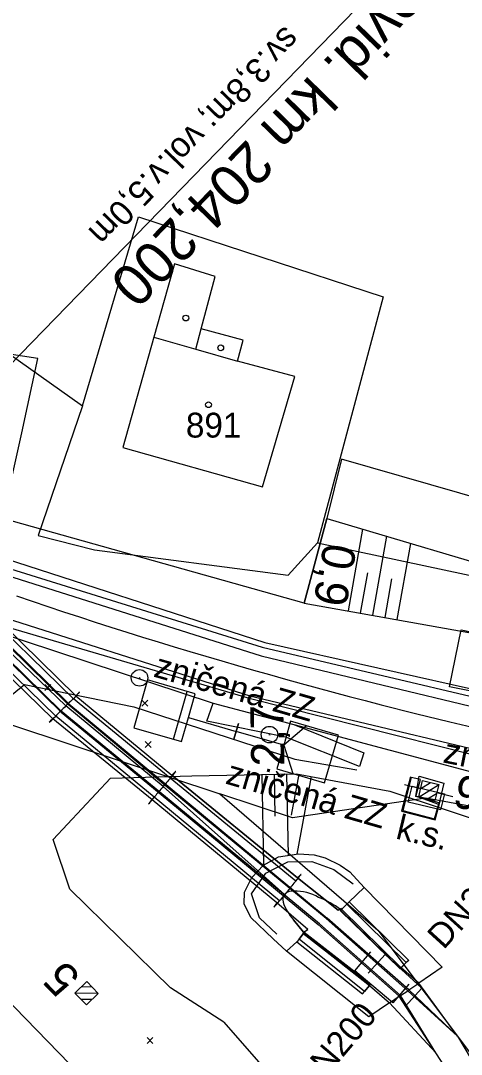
# Model space of a CAD drawing. Extents: x -800194 to -799078, y -1007177 to -1006597.
# Drawn here: x -799745.3 to -799718.7, y -1007007.9 to -1006945.4 of the extents above; entities that cross this region are included whole.
import ezdxf

# ---------------------------------------------------------------- set-up
doc = ezdxf.new("R2010")
doc.units = 0
for name, color, linetype in [('02_Osa_koleje', 7, 'Continuous'), ('_návrh', 7, 'Continuous'), ('Vrstva 11', 7, 'Continuous'), ('Vrstva 12', 7, 'Continuous'), ('Vrstva 16', 7, 'Continuous'), ('Vrstva 17', 7, 'Continuous'), ('Vrstva 18', 7, 'Continuous'), ('Vrstva 23', 7, 'Continuous'), ('Vrstva 25', 7, 'Continuous'), ('Vrstva 4', 7, 'Continuous'), ('Vrstva 43', 7, 'Continuous'), ('Vrstva 48', 7, 'Continuous'), ('Vrstva 49', 7, 'Continuous'), ('Vrstva 5', 7, 'Continuous'), ('Vrstva 50', 7, 'Continuous'), ('Vrstva 55', 7, 'Continuous'), ('Vrstva 56', 7, 'Continuous'), ('Vrstva 57', 7, 'Continuous'), ('Vrstva 59', 7, 'Continuous'), ('Vrstva 7', 7, 'Continuous')]:
    doc.layers.add(name, color=color, linetype=linetype)

msp = doc.modelspace()

# ---------------------------------------------------------------- linework, layer by layer
at = {"layer": '02_Osa_koleje'}
msp.add_lwpolyline([(-799745.551, -1006980.175), (-799744.604, -1006980.496), (-799743.656, -1006980.814), (-799742.707, -1006981.129), (-799741.757, -1006981.441), (-799740.806, -1006981.749), (-799739.853, -1006982.055), (-799738.9, -1006982.357), (-799737.946, -1006982.656), (-799736.991, -1006982.951), (-799736.034, -1006983.244), (-799735.077, -1006983.533), (-799734.119, -1006983.819), (-799733.16, -1006984.102), (-799732.199, -1006984.381), (-799731.238, -1006984.657), (-799730.276, -1006984.93), (-799729.313, -1006985.2), (-799728.35, -1006985.467), (-799727.385, -1006985.73), (-799726.419, -1006985.989), (-799725.453, -1006986.246), (-799724.485, -1006986.499), (-799723.517, -1006986.749)], dxfattribs=at)
msp.add_arc((-799651.022, -1006703.891), 292, 255.62486, 308.20516, dxfattribs=at)
at = {"layer": '_návrh'}
msp.add_lwpolyline([(-799821.595, -1006948.007), (-799811.064, -1006954.324), (-799803.753, -1006958.707), (-799793.935, -1006964.581), (-799784.224, -1006971.671), (-799782.913, -1006972.63), (-799767.418, -1006984.719), (-799752.333, -1006998.173), (-799735.027, -1007015.997), (-799721.623, -1007030.81), (-799713.555, -1007039.726), (-799713.111, -1007040.218)], dxfattribs=at)
at = {"layer": 'Vrstva 11'}
for p, q in [((-799721.139, -1006991.823), (-799722.111, -1006991.588)), ((-799721.233, -1006992.314), (-799720.055, -1006991.593)), ((-799721.138, -1006991.816), (-799720.542, -1006991.451)), ((-799720.718, -1006992.438), (-799720.18, -1006992.109)), ((-799720.167, -1006992.057), (-799719.195, -1006992.29)), ((-799740.621, -1007004.194), (-799742.031, -1007004.173)), ((-799740.986, -1007003.813), (-799741.655, -1007003.803)), ((-799741.001, -1007004.563), (-799741.662, -1007004.553))]:
    msp.add_line(p, q, dxfattribs=at)
for points in [[(-799721.022, -1006991.336), (-799720.05, -1006991.57), (-799720.284, -1006992.542), (-799721.256, -1006992.308)], [(-799741.336, -1007004.888), (-799742.033, -1007004.171), (-799741.316, -1007003.474), (-799740.619, -1007004.191)]]:
    msp.add_lwpolyline(points, close=True, dxfattribs=at)
at = {"layer": 'Vrstva 12'}
msp.add_lwpolyline([(-799721.236, -1006991.07), (-799719.737, -1006991.48), (-799720.049, -1006992.784), (-799721.435, -1006992.272), (-799721.236, -1006991.07)], dxfattribs=at)
at = {"layer": 'Vrstva 16'}
for p, q in [((-799725.462, -1006998.653), (-799724.55, -1006997.8)), ((-799728.219, -1007000.489), (-799728.813, -1006999.75)), ((-799721.913, -1007004.037), (-799726.857, -1006999.659)), ((-799727.952, -1007000.326), (-799728.231, -1007000.559)), ((-799728.231, -1007000.559), (-799724.23, -1007003.721)), ((-799727.258, -1006999.988), (-799722.361, -1007004.328)), ((-799728.622, -1007001.076), (-799729.241, -1007001.641)), ((-799721.857, -1007003.981), (-799721.255, -1007003.58)), ((-799723.028, -1007004.76), (-799722.434, -1007004.367))]:
    msp.add_line(p, q, dxfattribs=at)
for points in [[(-799726.857, -1006999.659), (-799736.574, -1006991.623), (-799742.439, -1006986.725), (-799754.518, -1006974.879), (-799763.734, -1006965.993), (-799777.293, -1006954.374), (-799779.945, -1006952.099), (-799783.722, -1006948.693)], [(-799783.708, -1006948.669), (-799779.9, -1006952.065), (-799777.252, -1006954.333), (-799763.672, -1006965.935), (-799754.476, -1006974.829), (-799742.393, -1006986.703), (-799736.524, -1006991.578), (-799726.778, -1006999.642)], [(-799784.356, -1006949.5), (-799780.347, -1006952.62), (-799777.716, -1006954.827), (-799764.168, -1006966.436), (-799754.935, -1006975.363), (-799742.857, -1006987.188), (-799736.94, -1006992.081), (-799727.324, -1007000.028)], [(-799727.258, -1006999.988), (-799736.887, -1006992.032), (-799742.859, -1006987.132), (-799754.894, -1006975.337), (-799764.135, -1006966.374), (-799777.698, -1006954.783), (-799780.331, -1006952.581), (-799784.321, -1006949.462)], [(-799779.465, -1006951.506), (-799778.251, -1006952.583), (-799776.738, -1006953.884), (-799763.224, -1006965.504), (-799753.999, -1006974.421), (-799741.964, -1006986.204), (-799736.168, -1006991.012), (-799728.577, -1006997.215), (-799726.123, -1006999.163)], [(-799727.952, -1007000.326), (-799729.82, -1006998.717), (-799737.37, -1006992.486), (-799743.358, -1006987.594), (-799755.401, -1006975.883), (-799764.592, -1006966.926), (-799778.073, -1006955.449), (-799779.598, -1006954.142), (-799780.843, -1006953.125)], [(-799724.268, -1007005.601), (-799729.241, -1007001.641), (-799730.043, -1007000.896), (-799731.391, -1006999.609), (-799731.807, -1006998.789), (-799731.776, -1006998.081), (-799731.332, -1006997.192), (-799730.628, -1006996.451), (-799729.736, -1006995.947), (-799728.528, -1006995.755), (-799727.566, -1006995.827), (-799726.904, -1006996.009), (-799726.001, -1006996.45), (-799725.419, -1006996.855), (-799724.55, -1006997.8), (-799719.837, -1007002.616)], [(-799719.837, -1007002.616), (-799721.255, -1007003.58), (-799722.309, -1007002.649), (-799722.019, -1007002.331), (-799725.605, -1006998.806), (-799725.462, -1006998.653), (-799721.848, -1007002.204), (-799722.019, -1007002.331)], [(-799726.123, -1006999.163), (-799725.923, -1006999.111), (-799725.92, -1006999.107), (-799725.969, -1006999.167)], [(-799725.605, -1006998.806), (-799725.969, -1006999.167), (-799725.978, -1006999.12)], [(-799727.324, -1007000.028), (-799722.434, -1007004.367), (-799722.361, -1007004.328), (-799721.913, -1007004.037), (-799721.857, -1007003.981), (-799726.778, -1006999.642)], [(-799724.23, -1007003.721), (-799724.534, -1007004.077), (-799728.488, -1007000.913), (-799728.199, -1007000.524)], [(-799728.231, -1007000.559), (-799728.25, -1007000.58), (-799728.201, -1007000.516), (-799728.199, -1007000.524), (-799728.219, -1007000.489)], [(-799728.488, -1007000.913), (-799728.622, -1007001.076), (-799724.647, -1007004.218), (-799724.534, -1007004.077)], [(-799724.23, -1007003.721), (-799723.028, -1007004.76), (-799724.268, -1007005.601)]]:
    msp.add_lwpolyline(points, dxfattribs=at)
for centre, major_axis, ratio, start_param, end_param in [((-799728.904, -1006998.513), (-0.566, -0.095), 0.888473, 4.396597, 6.415472), ((-799729.06, -1007000.766), (-2.796, -1.224), 0.88479, 3.718308, 4.259024), ((-799725.41, -1006997.773), (-4.211, 0.231), 0.818659, 0.330695, 0.676051), ((-799730.273, -1007003.369), (-6.212, -1.397), 0.847151, 3.77745, 4.035936), ((-799727.773, -1007000.273), (1.862, 1.216), 0.026669, 5.99696, 6.747447), ((-799726.195, -1006999.167), (-2.024, -1.323), 0.007629, 6.252324, 6.798297)]:
    msp.add_ellipse(centre, major_axis=major_axis, ratio=ratio, start_param=start_param, end_param=end_param, dxfattribs=at)
at = {"layer": 'Vrstva 17'}
for points in [[(-799726.806, -1006975.491), (-799728.174, -1006980.607), (-799746.39, -1006975.498), (-799745.242, -1006970.318), (-799744.263, -1006965.815), (-799756.721, -1006963.941)], [(-799695.807, -1006967.611), (-799698.37, -1006979.283), (-799711.621, -1006976.014), (-799725.913, -1006971.918), (-799726.806, -1006975.491)], [(-799746.564, -1006986.717), (-799745.074, -1006985.521), (-799738.458, -1006986.883), (-799728.745, -1006990.03), (-799724.988, -1006990.685)], [(-799721.747, -1006991.106), (-799722.3, -1006993.177), (-799720.272, -1006993.705), (-799719.96, -1006992.563)], [(-799729.82, -1007000.617), (-799730.868, -1006999.634), (-799731.355, -1006998.181), (-799730.498, -1006996.925), (-799729.155, -1006996.246), (-799727.711, -1006996.213), (-799726.389, -1006996.698), (-799725.227, -1006997.578)]]:
    msp.add_lwpolyline(points, dxfattribs=at)
at = {"layer": 'Vrstva 18'}
for p, q in [((-799754.68, -1006975.182), (-799715.262, -1006934.616)), ((-799728.577, -1006997.215), (-799736.168, -1006991.012)), ((-799729.364, -1006998.225), (-799736.701, -1006991.694)), ((-799729.82, -1006998.717), (-799737.37, -1006992.486)), ((-799726.123, -1006999.163), (-799728.577, -1006997.215)), ((-799727.952, -1007000.326), (-799729.82, -1006998.717)), ((-799725.98, -1006999.167), (-799722.374, -1007002.692)), ((-799722.407, -1007002.695), (-799725.98, -1006999.2)), ((-799722.019, -1007002.331), (-799725.605, -1006998.806)), ((-799728.813, -1006999.75), (-799728.219, -1007000.489)), ((-799728.199, -1007000.524), (-799728.488, -1007000.913)), ((-799724.23, -1007003.721), (-799728.231, -1007000.559)), ((-799728.199, -1007000.524), (-799728.201, -1007000.516)), ((-799724.197, -1007003.62), (-799728.169, -1007000.506)), ((-799728.168, -1007000.512), (-799724.201, -1007003.621)), ((-799724.534, -1007004.077), (-799728.488, -1007000.913)), ((-799724.238, -1007003.715), (-799728.25, -1007000.58)), ((-799722.374, -1007002.692), (-799722.372, -1007002.691))]:
    msp.add_line(p, q, dxfattribs=at)
for points in [[(-799728.689, -1006997.417), (-799736.272, -1006991.186), (-799742.111, -1006986.385), (-799754.178, -1006974.631), (-799763.368, -1006965.72), (-799777.061, -1006954.31)], [(-799776.738, -1006953.884), (-799763.224, -1006965.504), (-799753.999, -1006974.421), (-799741.964, -1006986.204), (-799736.168, -1006991.012)], [(-799736.701, -1006991.694), (-799742.573, -1006986.82), (-799754.68, -1006975.182), (-799763.887, -1006966.256), (-799777.391, -1006954.732)], [(-799737.37, -1006992.486), (-799743.358, -1006987.594), (-799755.401, -1006975.883), (-799764.592, -1006966.926), (-799778.073, -1006955.449)], [(-799729.664, -1006998.596), (-799737.245, -1006992.341), (-799743.186, -1006987.438), (-799755.222, -1006975.72), (-799764.444, -1006966.802), (-799777.959, -1006955.323)], [(-799725.98, -1006999.167), (-799725.92, -1006999.107), (-799725.923, -1006999.111), (-799722.309, -1007002.649)], [(-799725.969, -1006999.167), (-799725.98, -1006999.167), (-799725.98, -1006999.2), (-799725.968, -1006999.201)], [(-799725.605, -1006998.806), (-799725.969, -1006999.167), (-799725.968, -1006999.201), (-799722.404, -1007002.693)], [(-799728.201, -1007000.516), (-799728.25, -1007000.58), (-799728.231, -1007000.559)], [(-799724.194, -1007003.649), (-799728.201, -1007000.516), (-799728.169, -1007000.506)], [(-799728.169, -1007000.506), (-799728.168, -1007000.512), (-799728.199, -1007000.524)], [(-799722.309, -1007002.649), (-799722.321, -1007002.641), (-799722.374, -1007002.692), (-799722.407, -1007002.695), (-799722.404, -1007002.693), (-799722.372, -1007002.691), (-799722.019, -1007002.331), (-799722.309, -1007002.649)], [(-799724.201, -1007003.621), (-799724.197, -1007003.656), (-799724.534, -1007004.077), (-799724.23, -1007003.721)], [(-799724.194, -1007003.649), (-799724.238, -1007003.715), (-799724.23, -1007003.721)], [(-799724.197, -1007003.656), (-799724.194, -1007003.649), (-799724.197, -1007003.62), (-799724.201, -1007003.621)]]:
    msp.add_lwpolyline(points, dxfattribs=at)
for centre, major_axis, ratio, start_param, end_param in [((-799742.548, -1006987.401), (-0.826, -1.378), 0.12501, 3.399125, 3.961351), ((-799742.949, -1006987.371), (1.204, 1.399), 0.014573, 5.978594, 6.879596), ((-799742.617, -1006986.915), (0.711, 0.695), 0.037234, 0.742353, 2.460401), ((-799742.474, -1006986.496), (1.116, 1.298), 0.059378, 3.418673, 3.953091), ((-799742.2, -1006986.605), (-1.386, -1.202), 0.01146, 5.69132, 6.569057), ((-799736.745, -1006991.75), (0.647, 0.768), 0.002373, 0.747313, 2.45121), ((-799736.897, -1006992.163), (-0.963, -1.369), 0.041864, 3.408659, 3.947328), ((-799737.23, -1006992.158), (1.296, 1.385), 0.007101, 5.99726, 6.885866), ((-799736.715, -1006991.366), (0.854, 1.349), 0.064947, 3.376238, 3.945747), ((-799736.371, -1006991.391), (-1.212, -1.352), 0.012722, 5.667277, 6.576621), ((-799729.164, -1006998.01), (-0.65, -0.786), 0.017237, 3.872792, 5.567675), ((-799729.601, -1006998.375), (1.227, 1.391), 0.038982, 5.50568, 5.9942), ((-799729.675, -1006998.422), (1.311, 1.425), 0.009263, 6.006131, 6.851805), ((-799728.904, -1006998.513), (-0.566, -0.095), 0.888473, 4.396597, 6.415472), ((-799729.06, -1007000.766), (2.796, 1.224), 0.88479, 0.576715, 1.117431), ((-799728.95, -1006997.634), (-1.036, -1.326), 0.024932, 0.238319, 0.779035), ((-799725.41, -1006997.773), (-4.211, 0.231), 0.818659, 0.330695, 0.676051), ((-799730.273, -1007003.369), (-6.212, -1.397), 0.847151, 3.77745, 4.035936), ((-799728.754, -1006997.452), (-1.245, -1.521), 0.021997, 5.712311, 6.543003), ((-799727.773, -1007000.273), (1.862, 1.216), 0.026669, 5.99696, 6.747447), ((-799726.195, -1006999.167), (-2.024, -1.323), 0.007629, 6.252324, 6.798297)]:
    msp.add_ellipse(centre, major_axis=major_axis, ratio=ratio, start_param=start_param, end_param=end_param, dxfattribs=at)
at = {"layer": 'Vrstva 23'}
msp.add_lwpolyline([(-799721.159, -1006991.27), (-799721.712, -1006991.14), (-799722.223, -1006993.135), (-799720.312, -1006993.651), (-799720.015, -1006992.683), (-799721.422, -1006992.285), (-799721.159, -1006991.27)], dxfattribs=at)
at = {"layer": 'Vrstva 25'}
msp.add_lwpolyline([(-799721.886, -1006992.632), (-799721.652, -1006991.66), (-799719.708, -1006992.128), (-799719.942, -1006993.1), (-799721.886, -1006992.632)], dxfattribs=at)
at = {"layer": 'Vrstva 4'}
for points in [[(-799766.319, -1006970.565), (-799760.949, -1006972.542), (-799747.638, -1006977.46), (-799730.549, -1006982.982), (-799710.066, -1006987.578), (-799704.728, -1006988.346), (-799693.001, -1006990.373), (-799682.434, -1006991.64), (-799671.27, -1006992.619), (-799659.31, -1006993.026), (-799648.69, -1006993.125), (-799637.398, -1006992.704), (-799625.913, -1006992.175), (-799614.965, -1006990.831), (-799603.911, -1006989.312), (-799592.728, -1006987.172), (-799581.605, -1006984.547), (-799570.583, -1006981.598), (-799559.909, -1006978.216), (-799542.956, -1006972.25), (-799531.79, -1006967.658), (-799521.285, -1006962.191), (-799511.236, -1006957.129)], [(-799779.678, -1006964.304), (-799766.319, -1006970.565), (-799761.253, -1006973.176), (-799747.77, -1006978.421), (-799730.774, -1006983.8), (-799710.333, -1006988.709), (-799704.916, -1006989.741), (-799693.131, -1006991.407), (-799682.585, -1006992.929), (-799671.325, -1006993.879), (-799659.363, -1006994.45), (-799648.66, -1006994.501), (-799637.23, -1006994.127), (-799626.066, -1006993.335), (-799614.788, -1006992.17), (-799603.669, -1006990.506), (-799592.467, -1006988.452), (-799581.281, -1006985.916), (-799570.22, -1006982.998), (-799559.296, -1006979.606), (-799542.375, -1006973.485), (-799531.236, -1006968.774), (-799520.48, -1006963.762), (-799510.394, -1006958.536)], [(-799776.864, -1006969.085), (-799770.965, -1006971.646), (-799761.91, -1006975.649), (-799748.544, -1006980.777), (-799731.457, -1006986.215), (-799711.132, -1006991.054), (-799705.482, -1006992.16), (-799693.53, -1006994.084), (-799682.801, -1006995.384), (-799671.514, -1006996.319), (-799659.449, -1006996.851), (-799648.588, -1006996.949), (-799637.262, -1006996.573), (-799625.835, -1006995.773), (-799614.546, -1006994.586), (-799603.199, -1006992.945), (-799591.969, -1006990.857), (-799580.647, -1006988.335), (-799569.534, -1006985.311), (-799558.557, -1006981.947), (-799541.405, -1006975.739), (-799530.263, -1006971.071), (-799519.455, -1006966), (-799509.248, -1006960.724)], [(-799776.864, -1006969.085), (-799771.262, -1006971.982), (-799762.131, -1006976.093), (-799748.706, -1006981.286), (-799731.51, -1006986.353), (-799711.222, -1006991.459), (-799705.527, -1006992.587), (-799693.582, -1006994.543), (-799682.85, -1006995.904), (-799671.5, -1006996.805), (-799659.556, -1006997.356), (-799648.616, -1006997.341), (-799637.276, -1006997.071), (-799625.828, -1006996.297), (-799614.43, -1006995.109), (-799603.18, -1006993.475), (-799591.849, -1006991.264), (-799580.564, -1006988.698), (-799569.449, -1006985.746), (-799558.385, -1006982.386), (-799541.268, -1006976.227), (-799530.102, -1006971.505), (-799519.398, -1006966.36), (-799509.087, -1006961.127)], [(-799779.011, -1006963.023), (-799770.632, -1006967.944), (-799766.319, -1006970.565), (-799761.021, -1006972.82), (-799747.748, -1006977.966), (-799730.719, -1006983.271), (-799710.195, -1006988.108), (-799704.765, -1006989.181), (-799693.072, -1006990.965), (-799682.554, -1006992.238), (-799671.266, -1006993.222), (-799659.388, -1006993.765), (-799648.658, -1006993.824), (-799637.385, -1006993.531), (-799625.769, -1006992.728), (-799614.9, -1006991.542), (-799603.91, -1006989.963), (-799592.572, -1006987.892), (-799581.421, -1006985.419), (-799570.327, -1006982.332), (-799559.429, -1006979.066), (-799542.601, -1006973.013), (-799531.454, -1006968.25), (-799520.744, -1006963.214)], [(-799776.864, -1006969.085), (-799771.693, -1006972.522), (-799762.217, -1006976.394), (-799748.898, -1006981.647), (-799733.68, -1006986.66), (-799728.795, -1006987.945), (-799711.349, -1006992.599), (-799705.744, -1006994.116), (-799693.689, -1006996.09), (-799689.347, -1006996.226), (-799688.222, -1006996.296), (-799683.105, -1006997.407), (-799671.667, -1006998.275)], [(-799734.064, -1006987.737), (-799733.68, -1006986.66), (-799728.795, -1006987.945), (-799724.58, -1006989.646), (-799724.833, -1006990.487), (-799729.281, -1006988.715), (-799734.064, -1006987.737)]]:
    msp.add_lwpolyline(points, dxfattribs=at)
at = {"layer": 'Vrstva 43'}
for points in [[(-799721.858, -1007003.626), (-799722.831, -1007004.768), (-799725.115, -1007002.822), (-799724.142, -1007001.68)], [(-799724.303, -1007002.961), (-799723.293, -1007001.851), (-799721.075, -1007003.871), (-799722.084, -1007004.98)]]:
    msp.add_lwpolyline(points, dxfattribs=at)
at = {"layer": 'Vrstva 48'}
for p, q in [((-799725.506, -1006981.082), (-799724.627, -1006976.139)), ((-799724.029, -1006981.344), (-799723.18, -1006976.569)), ((-799722.552, -1006981.607), (-799721.733, -1006977)), ((-799724.767, -1006981.213), (-799724.335, -1006978.784)), ((-799723.291, -1006981.476), (-799722.873, -1006979.13)), ((-799730.742, -1006990.964), (-799730.628, -1006996.451)), ((-799729.993, -1006990.948), (-799729.94, -1006993.49)), ((-799729.243, -1006990.933), (-799729.14, -1006995.852)), ((-799728.495, -1006990.947), (-799728.955, -1006993.422)), ((-799727.758, -1006991.084), (-799728.628, -1006995.771))]:
    msp.add_line(p, q, dxfattribs=at)
at = {"layer": 'Vrstva 49'}
for p, q in [((-799743.837, -1006985.534), (-799743.483, -1006985.888)), ((-799743.837, -1006985.888), (-799743.483, -1006985.534)), ((-799737.98, -1006986.471), (-799737.626, -1006986.825)), ((-799737.98, -1006986.825), (-799737.626, -1006986.471)), ((-799737.782, -1006988.977), (-799737.428, -1006989.331)), ((-799737.782, -1006989.331), (-799737.428, -1006988.977)), ((-799718.907, -1007006.786), (-799721.255, -1007003.58)), ((-799718.907, -1007006.786), (-799721.857, -1007003.981)), ((-799720.214, -1007007.792), (-799723.028, -1007004.76)), ((-799722.361, -1007004.328), (-799722.434, -1007004.367)), ((-799720.214, -1007007.792), (-799722.434, -1007004.367)), ((-799720.214, -1007007.792), (-799722.361, -1007004.328)), ((-799737.668, -1007006.857), (-799737.314, -1007007.211)), ((-799737.668, -1007007.211), (-799737.314, -1007006.857))]:
    msp.add_line(p, q, dxfattribs=at)
for points in [[(-799728.174, -1006980.607), (-799726.806, -1006975.491), (-799714.47, -1006979.159), (-799704.928, -1006981.248), (-799699.097, -1006983.466), (-799688.779, -1006985.763), (-799678.423, -1006987.219), (-799669.363, -1006989.921)], [(-799728.174, -1006980.607), (-799715.637, -1006982.837), (-799705.851, -1006983.743), (-799700.586, -1006985.508), (-799691.67, -1006987.253), (-799678.693, -1006988.601), (-799669.363, -1006989.921)], [(-799733.039, -1007005.939), (-799736.26, -1007003.86), (-799742.34, -1006997.896), (-799743.342, -1006994.901), (-799739.871, -1006991.182), (-799734.968, -1006991.052), (-799728.642, -1006990.92), (-799723.01, -1006991.966), (-799716.141, -1006994.243), (-799710.319, -1006994.817)], [(-799723.028, -1007004.76), (-799724.268, -1007005.601), (-799729.241, -1007001.641), (-799730.043, -1007000.896), (-799731.391, -1006999.609), (-799731.807, -1006998.789), (-799731.776, -1006998.081), (-799731.332, -1006997.192), (-799730.628, -1006996.451), (-799729.736, -1006995.947), (-799728.528, -1006995.755), (-799727.566, -1006995.827), (-799726.904, -1006996.009), (-799726.001, -1006996.45), (-799725.419, -1006996.855), (-799724.55, -1006997.8), (-799719.837, -1007002.616), (-799721.255, -1007003.58)], [(-799718.907, -1007006.786), (-799721.913, -1007004.037), (-799721.857, -1007003.981)], [(-799733.039, -1007005.939), (-799730.086, -1007009.294), (-799720.161, -1007021.94)], [(-799718.907, -1007006.786), (-799714.515, -1007014.16), (-799704.214, -1007027.237), (-799692.017, -1007040.081), (-799674.887, -1007054.948)], [(-799676.078, -1007055.763), (-799692.866, -1007041.408), (-799705.479, -1007027.95), (-799715.681, -1007014.777), (-799720.214, -1007007.792)]]:
    msp.add_lwpolyline(points, dxfattribs=at)
at = {"layer": 'Vrstva 5'}
msp.add_lwpolyline([(-799715.76, -1006982.82), (-799716.453, -1006986.251), (-799719.394, -1006985.657), (-799718.701, -1006982.227)], close=True, dxfattribs=at)
at = {"layer": 'Vrstva 50'}
for p, q in [((-799738.172, -1006985.111), (-799738.076, -1006985.139)), ((-799730.319, -1006988.54), (-799730.223, -1006988.568))]:
    msp.add_line(p, q, dxfattribs=at)
for centre in [(-799738.124, -1006985.125), (-799730.271, -1006988.554)]:
    msp.add_circle(centre, 0.5, dxfattribs=at)
at = {"layer": 'Vrstva 55'}
for p, q in [((-799785.23, -1006937.71), (-799741.57, -1006968.68)), ((-799727.37, -1006976.97), (-799691.32, -1006984.61))]:
    msp.add_line(p, q, dxfattribs=at)
for points in [[(-799785.23, -1006937.71), (-799791.69, -1006959.99), (-799791.97, -1006960.97), (-799746.76, -1006987.67), (-799745.68, -1006988.03), (-799733.28, -1006992.13)], [(-799741.57, -1006968.68), (-799738.19, -1006957.26), (-799723.4, -1006962.09), (-799727.37, -1006976.97)], [(-799741.57, -1006968.68), (-799744.25, -1006976.52), (-799740.85, -1006977.38), (-799729.15, -1006978.91), (-799727.37, -1006976.97)], [(-799667.22, -1007009.16), (-799678.94, -1007000.07), (-799720.83, -1006992.39), (-799728.88, -1006993.59), (-799733.28, -1006992.13)], [(-799733.28, -1006992.13), (-799723.72, -1007000.38), (-799700.54, -1007031.23)]]:
    msp.add_lwpolyline(points, dxfattribs=at)
at = {"layer": 'Vrstva 56'}
for p, q in [((-799736.02, -1006960.1), (-799737.26, -1006964.54)), ((-799733.56, -1006960.86), (-799736.02, -1006960.1)), ((-799734.4, -1006964.04), (-799733.56, -1006960.86)), ((-799734.72, -1006965.27), (-799734.4, -1006964.04)), ((-799731.87, -1006964.71), (-799734.4, -1006964.04)), ((-799737.26, -1006964.54), (-799739.13, -1006971.21)), ((-799737.26, -1006964.54), (-799734.72, -1006965.27)), ((-799732.21, -1006965.99), (-799731.87, -1006964.71)), ((-799734.72, -1006965.27), (-799732.21, -1006965.99)), ((-799728.75, -1006966.91), (-799732.21, -1006965.99)), ((-799730.7, -1006973.58), (-799728.75, -1006966.91)), ((-799739.13, -1006971.21), (-799730.7, -1006973.58))]:
    msp.add_line(p, q, dxfattribs=at)
at = {"layer": 'Vrstva 59'}
for centre in [(-799735.327, -1006963.379), (-799733.217, -1006965.179), (-799733.957, -1006968.619)]:
    msp.add_circle(centre, 0.175, dxfattribs=at)
at = {"layer": 'Vrstva 7'}
for p, q in [((-799736.08, -1006988.826), (-799735.248, -1006985.944)), ((-799735.174, -1006987.526), (-799732.292, -1006988.358)), ((-799732.153, -1006987.878), (-799732.431, -1006988.838)), ((-799732.431, -1006988.838), (-799732.153, -1006987.878)), ((-799729.41, -1006989.19), (-799732.292, -1006988.358))]:
    msp.add_line(p, q, dxfattribs=at)
for points in [[(-799735.174, -1006987.526), (-799734.758, -1006986.085), (-799737.641, -1006985.253), (-799738.473, -1006988.136), (-799735.59, -1006988.967), (-799735.174, -1006987.526)], [(-799729.41, -1006989.19), (-799729.826, -1006990.631), (-799726.943, -1006991.463), (-799726.111, -1006988.58), (-799728.994, -1006987.749), (-799729.41, -1006989.19)], [(-799728.031, -1006988.026), (-799729.41, -1006989.19), (-799728.863, -1006990.909)]]:
    msp.add_lwpolyline(points, dxfattribs=at)

# ---------------------------------------------------------------- texts
at = {"layer": 'Vrstva 11'}
for s, rotation, p in [('9', 346.46066, (-799719.279, -1006992.868)), ('5', 134.15522, (-799741.611, -1007003.165))]:
    msp.add_text(s, height=2, rotation=rotation, dxfattribs=at).set_placement(p)
at = {"layer": 'Vrstva 18'}
for s, height, rotation, p in [('evid. km 204,200', 2.5, 225.63575, (-799722.248, -1006942.945)), ('sv.3,8m; vol.v.5,0m', 1.5, 226.13153, (-799729.335, -1006945.66))]:
    msp.add_text(s, height=height, rotation=rotation, dxfattribs=at).set_placement(p)
at = {"layer": 'Vrstva 25'}
msp.add_text('k.s.', height=1.5, rotation=346.46066, dxfattribs=at).set_placement((-799722.701, -1006994.822))
at = {"layer": 'Vrstva 43'}
for rotation, p in [(47.69501, (-799719.754, -1007001.594)), (49.57522, (-799727.74, -1007010.31))]:
    msp.add_text('DN200', height=1.5, rotation=rotation, dxfattribs=at).set_placement(p)
at = {"layer": 'Vrstva 48'}
for s, rotation, p in [('0,9', 259.91409, (-799726.972, -1006976.905)), ('2,7', 91.19538, (-799729.366, -1006990.445))]:
    msp.add_text(s, height=2, rotation=rotation, dxfattribs=at).set_placement(p)
at = {"layer": 'Vrstva 50'}
for rotation, p in [(343.90305, (-799737.339, -1006985.034)), (348.58947, (-799719.846, -1006990.228)), (343.90305, (-799732.994, -1006991.5))]:
    msp.add_text('zničená ZZ', height=1.5, rotation=rotation, dxfattribs=at).set_placement(p)
at = {"layer": 'Vrstva 57'}
msp.add_text('891', height=1.5, dxfattribs=at).set_placement((-799735.32, -1006970.602))

doc.saveas('drawing.dxf')
